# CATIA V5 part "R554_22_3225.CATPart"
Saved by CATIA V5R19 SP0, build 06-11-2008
Material "Steel": density 7860 kg/m3, Young's modulus 2e+11 Pa, Poisson ratio 0.266, thermal expansion 1.17e-05 1/K
Bounding box of the stored display mesh (mm): x -16.084 to 15, y -15.008 to 14.889, z 0.001 to 100
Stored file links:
  G:\Podręcznik\CD\Narzędzia\Arkusz Excel\Modele narzędzi\R554.22-3225.CATPart
  C:\Program Files\Dassault Systemes\B19\intel_a\startup\materials\Catalog.CATMaterial
  F:\OSTATNIE\DesignTable_R.xls
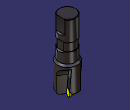
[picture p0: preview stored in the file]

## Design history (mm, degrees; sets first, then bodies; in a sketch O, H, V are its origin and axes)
Parameters
  CuttingType = "CUTTER"
  d = 25 mm {design table}
  D = 32 mm {design table}
  L = 100 mm {design table}
  l = 60 mm {design table}
  alfa = 15 deg {design table}
  gammap = 4 deg {design table}
  S = 3.18 mm {design table}
  rp = 5 mm
  x = 0.6282 mm {design table}
  gammaf = -2 deg {design table}
  z = 3 {design table}
  kat_miedzy_plytkami = 120 deg {design table}
  `dp'` = 9.9756 mm
Body1 "HOLDER" (main body), material "Steel"
  Sketch1 "sketch" on yz-plane, origin (0, 0, 0), H (0, 1, 0), V (0, 0, 1)
    line L1 (0, 0.6282) -> (11, 0.6282)
    line L2 (15, 4.6282) -> (15, 40)
    point P2 (15, 40)
    line L3 (15, 40) -> (15, 40)
    point P3 (12.5, 40)
    line L4 (12.5, 42.5904) -> (12.5, 58)
    point P4 (12.5, 58)
    line L5 (12.5, 58) -> (11.5, 58)
    line L6 (11.5, 58) -> (11.5, 70)
    line L7 (11.5, 70) -> (12.5, 70)
    point P7 (12.5, 70)
    line L8 (12.5, 70) -> (12.5, 99.2929)
    line L9 (12.5, 99.2929) -> (11.7929, 100)
    line L10 (11.7929, 100) -> (0, 100)
    point P10 (0, 100)
    line L11 (0, 100) -> (0, 0.6282)
    construction line L12 (0, -29.1199) -> (0, 199.3445)
    point P11 (0, -29.1199)
    line L13 (15, 40) -> (12.5, 42.5904)
    point P13 (15, 40)
    arc A1 centre (11, 4.6282) radius 4 from (15, 4.6282) to (11, 0.6282) cw
    point P17 (11, 4.6282)
    length L6 = 12 {= 0.2*l}
    distance P2 H = 40 {= L-l}
    length L9 = 1
    angle L8 L9 = 45
    distance L6 L8 = 1
    distance L8 L11 = 12.5 {= d/2}
    distance L10 L7 = 30 {= 0.5*l}
    distance P3 P4 = 18 {= 0.3*l}
    length L13 = 3.6 {= 0.2*(0.3*l)}
    distance L1 H = 0.6282 {= x}
    radius A1 = 4 {= 0.8*rp}
    distance P17 L11 = 11 {= D/2-rp}
    vertical: L2 V, L4 V, L6 V, L8 V, L11 V, L12 V
    horizontal: L3 H, L5 H, L7 H, L10 H
    coincidence: P7 L4, P10 V, P11 V, L3 P3, L4 P3, P2 P13
    tangency: A1 L2, A1 L1
  Shaft1: profile Sketch1, axis Z axis, angle 360
  Plane1: type Offset, Offset 2, RefPlane zx-plane
  Sketch2 on Plane1, origin (0, 2, 0), H (-1, 0, 0), V (0, 0, 1)
    line L1 (0, 0) -> (4.2605, 0)
    horizontal: L1 H
  Plane2 "gammap": type Angle, Angle -4 {= -gammap}, Direction Sketch2, RefPlane Plane1
  Sketch3 on zx-plane, origin (0, 0, 0), H (-1, 0, 0), V (0, 0, 1)
    line L1 (-10.5, 100) -> (-10.5, 80)
    line L2 (-10.5, 80) -> (-12.5, 78)
    line L3 (-12.5, 78) -> (-12.5, 72)
    line L4 (-12.5, 72) -> (-10.5, 70)
    point P5 (-10.5, 70)
    line L5 (-10.5, 70) -> (-10.5, 58)
    point P6 (-10.5, 58)
    line L6 (-10.5, 58) -> (-12.5, 56)
    point P7 (-12.5, 56)
    line L7 (-12.5, 56) -> (-16.5, 56)
    line L8 (-16.5, 56) -> (-16.5, 100)
    line L9 (-16.5, 100) -> (-10.5, 100)
    reference projected line E1 (-9.2929, 100) -> (9.2929, 100) from edge [face of Shaft1 from Sketch1.L9 | face of Shaft1 from Sketch1.L10]
    reference projected line E2 (-10, 70) -> (10, 70) from edge [face of Shaft1 from Sketch1.L7 | face of Shaft1 from Sketch1.L8]
    reference projected line E3 (-10, 58) -> (10, 58) from edge [face of Shaft1 from Sketch1.L4 | face of Shaft1 from Sketch1.L5]
    reference projected line E4 through (0, 0) direction (0, 1) from axis of face of Shaft1 from Sketch1.L8
    distance L3 L1 = 2
    angle L2 L1 = 45
    angle L6 L5 = 45
    distance L1 L8 = 6
    distance E4 L3 = 12.5 {= d/2}
    distance P7 L5 = 2
    length L3 = 6 {= 0.1*l}
    vertical: L1 V, L3 V, L5 V, L8 V
    perpendicularity: L4 L2
    coincidence: P7 L3, L9 E1, P5 E2, P6 E3
    horizontal: L7 H, L9 H
  Pocket1: profile Sketch3, direction (0, -1, 0), length 20, mirrored extent
  Sketch4 on Plane2, origin (0, 1.9903, 0.1392), H (-1, 0, 0), V (0, -0.0698, 0.9976)
    line L1 (16, 13.7491) -> (16, 0)
    point P1 (16, 0)
    distance V L1 = 16 {= D/2}
    coincidence: P1 H
    vertical: L1 V
  Plane3 "gammaf": type Angle, Angle -2 {= gammaf}, Direction Sketch4, RefPlane Plane2
  Plane4: type Offset, Offset 16 {= D/2}, RefPlane zx-plane
  Sketch5 on Plane4, origin (0, 16, 0), H (-1, 0, 0), V (0, 0, 1)
    point P1 (6, 0)
    line L1 (6, 0) -> (6, 25.1678)
    arc A1 centre (18, 25.1678) radius 12 from (6, 25.1678) to (16, 37) cw
    point P4 (16, 37)
    line L2 (16, 37) -> (16, 0)
    point P5 (16, 0)
    line L3 (16, 0) -> (6, 0)
    reference projected point E1 (0, 4.6282) from edge
    reference projected line E2 (-11.5, 40) -> (11.5, 40) from edge [face of Shaft1 from Sketch1.L2 | face of Shaft1 from Sketch1.L13]
    distance E1 L2 = 16 {= D/2}
    radius A1 = 12
    distance E2 P4 = 3
    distance L1 L2 = 10 {= 2*rp}
    coincidence: P1 H, P5 H
    vertical: L1 V, L2 V
    horizontal: L3 H
    tangency: A1 L1
  Pocket2: profile Sketch5, direction (0, -1, 0), up to Plane3
  CircPattern1: of Pocket2, instances 3 {= z}, angular step 120 {= kat_miedzy_plytkami}, axis from Z axis
  Sketch6 on Plane3, origin (-0.0891, 2.5445, 0.1779), H (-0.9994, -0.035, 0), V (0.0024, -0.0697, 0.9976)
    line L1 (16, 0) -> (16, 6.1909)
    point P1 (16, 0)
    distance V L1 = 16 {= D/2}
    coincidence: P1 H
    vertical: L1 V
  Plane5: type Angle, Angle 90, Direction Sketch6, RefPlane Plane3
  Plane6: type Offset, Offset 5 {= rp}, RefPlane Plane5, reversed
  Sketch7 on Plane6, origin (-10.9933, -0.3848, 0), H (0.035, -0.9994, 0), V (0, 0, 1)
    point P1 (-3.0597, 0)
    line L1 (-3.0597, 0) -> (-2.7112, 4.9878)
    line L2 (-2.7112, 4.9878) -> (0.4611, 4.7661)
    line L3 (0.4611, 4.7661) -> (0.1719, 0.6283)
    line L4 (0.1719, 0.6283) -> (-3.0597, 0)
    axis line L5 (-3.0597, 0) -> (2.7185, -0.4038)
    reference projected line E1 (-0.7991, 25.1764) -> (-2.5579, 0.0085) from edge [end face of Pocket2 | face of Pocket2 from Sketch5.L1]
    reference projected line E2 (-0.7991, 25.1764) -> (-2.5579, 0.0085) from edge [end face of Pocket2 | face of Pocket2 from Sketch5.L1]
    distance L1 L3 = 3.18 {= S}
    length L1 = 5 {= rp}
    angle L5 L4 = 15 {= alfa}
    distance L1 E2 = 0.5
    coincidence: P1 H
    perpendicularity: L2 L1
    parallelism: L5 L2, L1 E1
  Groove1: profile Sketch7, axis Sketch7.L2, angle 360
  CircPattern2: of Groove1, instances 3 {= z}, angular step 120 {= kat_miedzy_plytkami}, axis from Z axis
Body2 "CUTTER"
  Sketch8 "CUT" on yz-plane, origin (0, 0, 0), H (0, 1, 0), V (0, 0, 1)
    point P1 (11, 5)
    point P2 (0, 0.6282)
    line L1 (0, 0.6282) -> (8.5737, 0.6282)
    arc A1 centre (11, 5) radius 5 from (8.5737, 0.6282) to (15, 8) ccw
    point P4 (11, 5)
    point P5 (15, 8)
    line L2 (15, 8) -> (0, 8)
    point P6 (0, 8)
    line L3 (0, 8) -> (0, 0.6282)
    axis line L4 (0, 8) -> (16, 8)
    point P7 (16, 8)
    distance P1 H = 5 {= rp}
    distance P1 V = 11 {= D/2-rp}
    distance H L1 = 0.6282 {= x}
    length L4 = 16 {= D/2}
    distance P7 P5 = 1
    coincidence: P2 V, P6 V, P4 P1
    horizontal: L1 H, L2 H, L4 H
    vertical: L3 V
    tangency: A1 H
  Sketch9 "NOCUT" on yz-plane, origin (0, 0, 0), H (0, 1, 0), V (0, 0, 1)
    point P1 (0, 8)
    line L1 (0, 8) -> (15, 8)
    point P2 (15, 8)
    line L2 (15, 8) -> (15, 40)
    line L3 (15, 40) -> (12.5, 40)
    line L4 (12.5, 40) -> (12.5, 58)
    line L5 (12.5, 58) -> (11.5, 58)
    line L6 (11.5, 58) -> (11.5, 70)
    line L7 (11.5, 70) -> (12.5, 70)
    point P8 (12.5, 70)
    line L8 (12.5, 70) -> (12.5, 100)
    line L9 (12.5, 100) -> (0, 100)
    point P10 (0, 100)
    line L10 (0, 100) -> (0, 8)
    reference projected line E1 (11.5, 8) -> (0, 8) from Sketch8.L2
    reference projected point E2 (15, 8) from vertex [element of Sketch8 | element of Sketch8]
    reference projected line E3 (-11.7929, 100) -> (11.7929, 100) from edge [face of Shaft1 from Sketch1.L9 | face of Shaft1 from Sketch1.L10]
    length L8 = 30 {= 0.5*l}
    length L6 = 12 {= 0.2*l}
    length L4 = 18 {= 0.3*l}
    distance L8 L10 = 12.5 {= d/2}
    distance L6 L8 = 1
    coincidence: P1 V, P8 L4, P10 V, E1 L1, P2 E2, L9 E3
    horizontal: L1 H, L3 H, L5 H, L7 H, L9 H
    vertical: L2 V, L4 V, L6 V, L8 V, L10 V
  Shaft2: profile Sketch7, axis Sketch7.L2, angle 360
  CircPattern3: of Shaft2, instances 3 {= z}, angular step 120 {= kat_miedzy_plytkami}, axis from Z axis
Relations
  design table, configuration 2, drives d, D, L, l, alfa, gammap, S, x, gammaf, z, kat_miedzy_plytkami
